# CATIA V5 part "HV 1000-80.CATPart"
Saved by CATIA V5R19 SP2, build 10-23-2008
Part number: HV 1000-80
Bounding box of the stored display mesh (mm): x -24.865 to 24.865, y -24.997 to 24.997, z 0 to 217
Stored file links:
  C:\Users\Bora\Desktop\3D KATI MODEL- CATIA PART\HV serisi\HV 1000\HV 1000-80.CATPart
  C:\Program Files\Dassault Systemes\B19\intel_a\reffiles\standard\MetricThickPitch.txt
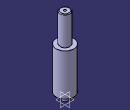
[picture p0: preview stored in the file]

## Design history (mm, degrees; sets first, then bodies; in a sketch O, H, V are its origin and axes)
Body1 (main body)
  Sketch1 on yz-plane, origin (0, 0, 0), H (0, 1, 0), V (0, 0, 1)
    point P1 (14, 215)
    point P3 (14, 215)
    point P8 (8, 17)
    point P10 (8, 1)
    point P11 (8, 17)
    point P12 (8, 1)
    arc A1 centre (12, 215) radius 2 from (14, 215) to (12, 217) ccw
    line L1 (14, 215) -> (14, 136)
    arc A2 centre (8, 18) radius 1 from (8, 19) to (8, 17) ccw
    line L2 (7, 0) -> (8, 1)
    line L3 (8, 17) -> (8, 1)
    line L4 (0, 0) -> (7, 0)
    line L5 (8, 19) -> (25, 19)
    line L6 (14, 136) -> (25, 136)
    line L7 (12, 217) -> (0, 217)
    point P13 (0, 217)
    line L8 (25, 136) -> (25, 19)
    horizontal: L4 H, L5 H, L6 H
    coincidence: P13 V, P1 P3, P8 P11, P10 P12
    tangency: L7 A1
    vertical: L8 V
  Shaft1: profile Sketch1, axis Sketch1.V, angle 360
  Sketch2 on face of Shaft1 from Sketch1.L4, origin (0, 0, 0), H (1, 0, 0), V (0, -1, 0)
    point P1 (0, 0)
  Hole1: placed by Sketch2, at (0, 0, 0) direction (0, 0, 1), diameter 13.835, depth 19, threaded "M16", thread diameter 16, thread depth 19, pitch 2
  Sketch3 on face of Shaft1 from Sketch1.L7, origin (0, 0, 217), H (1, 0, 0), V (0, 1, 0)
    point P1 (0, 0)
  Hole2: placed by Sketch3, at (0, 0, 217) direction (0, 0, -1), diameter 6.647, depth 15, threaded "M8", thread diameter 8, thread depth 15, pitch 1.25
